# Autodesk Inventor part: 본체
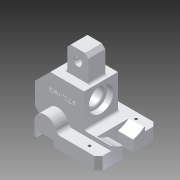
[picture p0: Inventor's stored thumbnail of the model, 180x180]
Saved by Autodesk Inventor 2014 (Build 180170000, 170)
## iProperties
Created: 2016-11
Part Number: 본체
Material: 알루미늄 6061
Document SubType Name: Modeling
Designer: owner
Density: 2.71 g/cm^3
Appearance: 알루미늄 - 평지
Mass: 462.697 g
Surface Area: 317.767 cm^2
Volume: 170.737 cm^3
Author: owner
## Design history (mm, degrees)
sketch "스케치2"
  geometry: L1 (45, -35)-(-18, -35); L2 (45, 35)-(-18, 35); L3 (45, -35)-(45, -6); L4 (45, -6)-(-18, -6); L5 (45, 35)-(45, 6); L6 (45, 6)-(-18, 6); L7 (-18, 6)-(-18, 35); L8 (-18, -6)-(-18, -35); 1 further point
  constraints: 16 end point, 4 perpendicular, 1 collinear
extrude "돌출1" new body sketch "스케치2" distance "d11" = 15; taper "d12" = 0 deg
node "작업 평면1"
sketch "스케치3"
  geometry: L1 (-13, 15)-(-13, 0); L2 (-10, 0)-(-10, 7); L3 (-10, 7)-(10, 7); L4 (10, 7)-(10, 0); L5 (-10, 0)-(10, 0); L6 (13, 15)-(13, 0); L7 (-13, 0)-(13, 0); A1 r 13 centre (0, 15) between (13, 15) and (-13, 15); 2 further points
  constraints: 14 end point, 2 point on circle, 2 tangent, 1 centre point, 1 coincident, 1 perpendicular
extrude "돌출2" join sketch "스케치3" stored distance "d19" = 20; taper "d20" = 0 deg
extrude "돌출3" cut sketch "스케치3" stored distance "d21" = 20; taper "d22" = 0 deg
sketch "스케치4"
  geometry: L1 (-45, 0)-(-45, 15) reference; L2 (28, 7)-(8, 7) reference; L3 (-13, 60)-(27, 60); L4 (45, 12)-(-13, 12); L5 (45, 12)-(45, 42); L6 (45, 42)-(27, 60); L7 (-13, 12)-(-13, 60); L8 (-8, 60)-(-8, 86); L9 (-4, 90)-(13, 90); L10 (17, 86)-(17, 60); L11 (-8, 86)-(-4, 90); L12 (13, 90)-(17, 86); L13 (-45, 0)-(-45, 20); L14 (-45, 20)-(-13, 20); L15 (-13, 20)-(-13, 0); L16 (-13, 0)-(-45, 0); A1 r 13 centre (18, 15) between (31, 15) and (5, 15) reference; 3 further points
  constraints: 28 end point, 7 point on line, 5 perpendicular, 2 parallel
extrude "돌출4" join sketch "스케치4" stored distance "d36" = 40; taper "d37" = 0 deg
extrude "돌출5" join sketch "스케치4" stored distance "d38" = 20; taper "d39" = 0 deg
sketch "스케치5"
  geometry: 2 further points
node "작업 평면2"
extrude "돌출6" join sketch "스케치4" stored distance "d43" = 40; taper "d44" = 0 deg
sketch "스케치6"
  geometry: C1 r 29 at (0, 20); 1 further point
  constraints: 1 centre point
sketch "스케치7"
  geometry: L1 (-42, 14)-(-22, 14); L2 (-22, 14)-(-22, 26); L3 (-22, 26)-(-42, 26); L4 (-42, 26)-(-42, 14); 1 further point
  constraints: 8 end point, 1 parallel, 1 perpendicular
extrude "돌출7" cut sketch "스케치6" distance "d52" = 18; taper "d53" = 0 deg
extrude "돌출8" cut sketch "스케치7" distance "d54" = 18; taper "d55" = 0 deg
sketch "스케치8"
  geometry: L1 (45, 18.894)-(45, 6) reference; L2 (45, -6)-(45, -18.894) reference; 3 further points
sketch "스케치9"
  geometry: L1 (45, 0)-(-8, 0) reference; 2 further points
hole "구멍1" sketch "스케치9" at (-4.5, -77) diameter "d59" = 8; stored, may be unused: countersink angle "d63" = 90 deg, drill point angle "d65" = 118 deg; dims "d60" = 6, "d61" = 4, "d62" = 2, "d64" = 8
hole "구멍2" sketch "스케치5" diameter "d66" = 20; stored, may be unused: countersink angle "d70" = 90 deg, drill point angle "d72" = 118 deg; dims "d67" = 6, "d68" = 29, "d69" = 7, "d71" = 8
hole "구멍3" sketch "스케치8" diameter "d73" = 3.242; stored, may be unused: countersink angle "d77" = 90 deg, drill point angle "d79" = 118 deg; dims "d74" = 6, "d75" = 29, "d76" = 7, "d78" = 8
chamfer "모따기1" distance "d84" = 5; stored, may be unused: second distance "d85" = 2, angle "d86" = 45 deg
fillet "모깎기1" dims "d87" = 3, "d106" = 5
chamfer "모따기2" distance "d88" = 1; stored, may be unused: second distance "d89" = 2, angle "d90" = 45 deg
chamfer "모따기3" distance "d91" = 1; stored, may be unused: second distance "d92" = 2, angle "d93" = 45 deg
chamfer "모따기4" distance "d94" = 1; stored, may be unused: second distance "d95" = 2, angle "d96" = 45 deg
sketch "스케치12"
  geometry: L1 (5, 6)-(-13, 6) reference; L2 (5, -6)-(-13, -6) reference; L3 (-13, 6)-(-13, -6); L4 (-13, -6)-(5, -6); L5 (5, -6)-(5, 6); L6 (5, 6)-(-13, 6); 1 further point
  constraints: 8 end point, 2 collinear, 2 perpendicular
extrude "돌출9" join sketch "스케치12" stored distance "d97" = 40; taper "d98" = 0 deg
sketch "스케치13"
  geometry: 2 further points
  constraints: 1 other
feature "엠보싱2" sketch "스케치13" dims "d21" = 20, "d101" = 0.5, "d102" = 0
chamfer "모따기5" distance "d103" = 4; stored, may be unused: second distance "d104" = 2, angle "d105" = 45 deg
node "솔리드1"
mirror "대칭1"
other parameters: "d13" = 35
